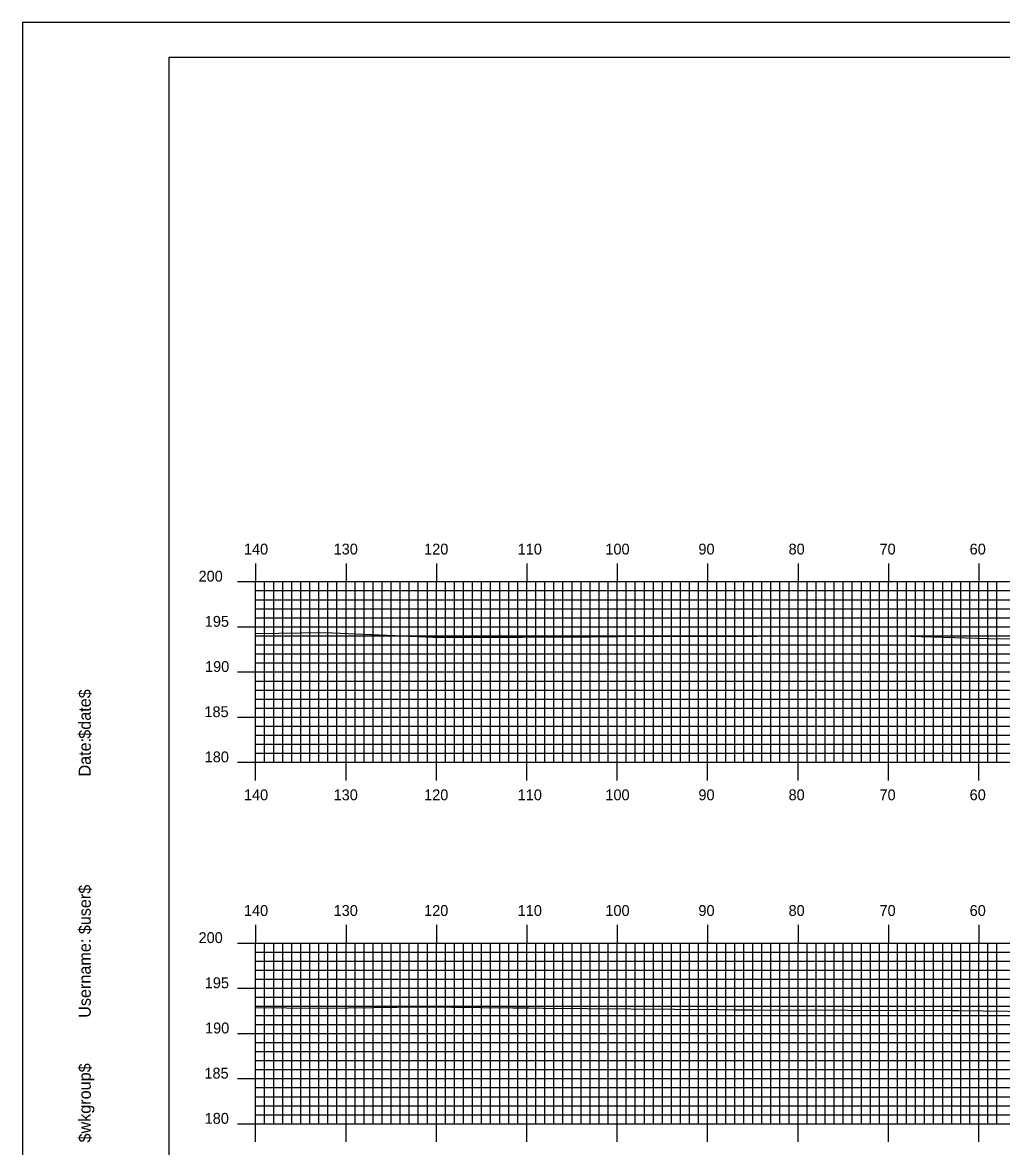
# Model space of a CAD drawing. Extents: x 1798781 to 1799124, y 442591 to 442811.
# Drawn here: x 1798781.2 to 1798889.5, y 442686.2 to 442810.5 of the extents above; entities that cross this region are included whole.
import ezdxf

# ---------------------------------------------------------------- set-up
doc = ezdxf.new("R2010")
doc.units = 0
for name, color, linetype in [('BORDER', 7, 'Continuous'), ('H_V ANNOTATION', 7, 'Continuous'), ('MAJOR', 7, 'Continuous'), ('MINOR', 7, 'Continuous'), ('PLOT BOUNDARY', 7, 'Continuous'), ('S_Roadway_Centerline', 7, 'Continuous')]:
    doc.layers.add(name, color=color, linetype=linetype)

msp = doc.modelspace()

# ---------------------------------------------------------------- linework, layer by layer
at = {"layer": 'BORDER'}
msp.add_lwpolyline([(1798797.38, 442596.67), (1799117.38, 442596.67), (1799117.38, 442806.67), (1798797.38, 442806.67)], close=True, dxfattribs=at)
at = {"layer": 'MAJOR'}
for p, q in [((1798806.98, 442750.67), (1798806.98, 442748.67)), ((1798816.98, 442750.67), (1798816.98, 442748.67)), ((1798826.98, 442750.67), (1798826.98, 442748.67)), ((1798836.98, 442750.67), (1798836.98, 442748.67)), ((1798846.98, 442750.67), (1798846.98, 442748.67)), ((1798856.98, 442750.67), (1798856.98, 442748.67)), ((1798866.98, 442750.67), (1798866.98, 442748.67)), ((1798876.98, 442750.67), (1798876.98, 442748.67)), ((1798886.98, 442750.67), (1798886.98, 442748.67)), ((1798804.98, 442748.67), (1798806.98, 442748.67)), ((1798806.98, 442748.67), (1799086.98, 442748.67)), ((1798806.98, 442728.67), (1798806.98, 442748.67)), ((1798806.98, 442728.67), (1798806.98, 442748.67)), ((1798806.98, 442748.67), (1799086.98, 442748.67)), ((1798816.98, 442728.67), (1798816.98, 442748.67)), ((1798826.98, 442728.67), (1798826.98, 442748.67)), ((1798836.98, 442728.67), (1798836.98, 442748.67)), ((1798846.98, 442728.67), (1798846.98, 442748.67)), ((1798856.98, 442728.67), (1798856.98, 442748.67)), ((1798866.98, 442728.67), (1798866.98, 442748.67)), ((1798876.98, 442728.67), (1798876.98, 442748.67)), ((1798886.98, 442728.67), (1798886.98, 442748.67)), ((1798804.98, 442743.67), (1798806.98, 442743.67)), ((1798806.98, 442743.67), (1799086.98, 442743.67)), ((1798804.98, 442738.67), (1798806.98, 442738.67)), ((1798806.98, 442738.67), (1799086.98, 442738.67)), ((1798804.98, 442733.67), (1798806.98, 442733.67)), ((1798806.98, 442733.67), (1799086.98, 442733.67)), ((1798804.98, 442728.67), (1798806.98, 442728.67)), ((1798806.98, 442728.67), (1799086.98, 442728.67)), ((1798806.98, 442728.67), (1799086.98, 442728.67)), ((1798806.98, 442726.66), (1798806.98, 442728.67)), ((1798816.98, 442726.66), (1798816.98, 442728.67)), ((1798826.98, 442726.66), (1798826.98, 442728.67)), ((1798836.98, 442726.66), (1798836.98, 442728.67)), ((1798846.98, 442726.66), (1798846.98, 442728.67)), ((1798856.98, 442726.66), (1798856.98, 442728.67)), ((1798866.98, 442726.66), (1798866.98, 442728.67)), ((1798876.98, 442726.66), (1798876.98, 442728.67)), ((1798886.98, 442726.66), (1798886.98, 442728.67)), ((1798806.98, 442710.67), (1798806.98, 442708.67)), ((1798816.98, 442710.67), (1798816.98, 442708.67)), ((1798826.98, 442710.67), (1798826.98, 442708.67)), ((1798836.98, 442710.67), (1798836.98, 442708.67)), ((1798846.98, 442710.67), (1798846.98, 442708.67)), ((1798856.98, 442710.67), (1798856.98, 442708.67)), ((1798866.98, 442710.67), (1798866.98, 442708.67)), ((1798876.98, 442710.67), (1798876.98, 442708.67)), ((1798886.98, 442710.67), (1798886.98, 442708.67)), ((1798804.98, 442708.67), (1798806.98, 442708.67)), ((1798806.98, 442708.67), (1799086.98, 442708.67)), ((1798806.98, 442688.67), (1798806.98, 442708.67)), ((1798806.98, 442688.67), (1798806.98, 442708.67)), ((1798806.98, 442708.67), (1799086.98, 442708.67)), ((1798816.98, 442688.67), (1798816.98, 442708.67)), ((1798826.98, 442688.67), (1798826.98, 442708.67)), ((1798836.98, 442688.67), (1798836.98, 442708.67)), ((1798846.98, 442688.67), (1798846.98, 442708.67)), ((1798856.98, 442688.67), (1798856.98, 442708.67)), ((1798866.98, 442688.67), (1798866.98, 442708.67)), ((1798876.98, 442688.67), (1798876.98, 442708.67)), ((1798886.98, 442688.67), (1798886.98, 442708.67)), ((1798804.98, 442703.67), (1798806.98, 442703.67)), ((1798806.98, 442703.67), (1799086.98, 442703.67)), ((1798804.98, 442698.67), (1798806.98, 442698.67)), ((1798806.98, 442698.67), (1799086.98, 442698.67)), ((1798804.98, 442693.67), (1798806.98, 442693.67)), ((1798806.98, 442693.67), (1799086.98, 442693.67)), ((1798804.98, 442688.67), (1798806.98, 442688.67)), ((1798806.98, 442688.67), (1799086.98, 442688.67)), ((1798806.98, 442688.67), (1799086.98, 442688.67)), ((1798806.98, 442686.66), (1798806.98, 442688.67)), ((1798816.98, 442686.66), (1798816.98, 442688.67)), ((1798826.98, 442686.66), (1798826.98, 442688.67)), ((1798836.98, 442686.66), (1798836.98, 442688.67)), ((1798846.98, 442686.66), (1798846.98, 442688.67)), ((1798856.98, 442686.66), (1798856.98, 442688.67)), ((1798866.98, 442686.66), (1798866.98, 442688.67)), ((1798876.98, 442686.66), (1798876.98, 442688.67)), ((1798886.98, 442686.66), (1798886.98, 442688.67))]:
    msp.add_line(p, q, dxfattribs=at)
at = {"layer": 'MINOR'}
for p, q in [((1798807.98, 442728.67), (1798807.98, 442748.67)), ((1798808.98, 442728.67), (1798808.98, 442748.67)), ((1798809.98, 442728.67), (1798809.98, 442748.67)), ((1798810.98, 442728.67), (1798810.98, 442748.67)), ((1798811.98, 442728.67), (1798811.98, 442748.67)), ((1798812.98, 442728.67), (1798812.98, 442748.67)), ((1798813.98, 442728.67), (1798813.98, 442748.67)), ((1798814.98, 442728.67), (1798814.98, 442748.67)), ((1798815.98, 442728.67), (1798815.98, 442748.67)), ((1798817.98, 442728.67), (1798817.98, 442748.67)), ((1798818.98, 442728.67), (1798818.98, 442748.67)), ((1798819.98, 442728.67), (1798819.98, 442748.67)), ((1798820.98, 442728.67), (1798820.98, 442748.67)), ((1798821.98, 442728.67), (1798821.98, 442748.67)), ((1798822.98, 442728.67), (1798822.98, 442748.67)), ((1798823.98, 442728.67), (1798823.98, 442748.67)), ((1798824.98, 442728.67), (1798824.98, 442748.67)), ((1798825.98, 442728.67), (1798825.98, 442748.67)), ((1798827.98, 442728.67), (1798827.98, 442748.67)), ((1798828.98, 442728.67), (1798828.98, 442748.67)), ((1798829.98, 442728.67), (1798829.98, 442748.67)), ((1798830.98, 442728.67), (1798830.98, 442748.67)), ((1798831.98, 442728.67), (1798831.98, 442748.67)), ((1798832.98, 442728.67), (1798832.98, 442748.67)), ((1798833.98, 442728.67), (1798833.98, 442748.67)), ((1798834.98, 442728.67), (1798834.98, 442748.67)), ((1798835.98, 442728.67), (1798835.98, 442748.67)), ((1798837.98, 442728.67), (1798837.98, 442748.67)), ((1798838.98, 442728.67), (1798838.98, 442748.67)), ((1798839.98, 442728.67), (1798839.98, 442748.67)), ((1798840.98, 442728.67), (1798840.98, 442748.67)), ((1798841.98, 442728.67), (1798841.98, 442748.67)), ((1798842.98, 442728.67), (1798842.98, 442748.67)), ((1798843.98, 442728.67), (1798843.98, 442748.67)), ((1798844.98, 442728.67), (1798844.98, 442748.67)), ((1798845.98, 442728.67), (1798845.98, 442748.67)), ((1798847.98, 442728.67), (1798847.98, 442748.67)), ((1798848.98, 442728.67), (1798848.98, 442748.67)), ((1798849.98, 442728.67), (1798849.98, 442748.67)), ((1798850.98, 442728.67), (1798850.98, 442748.67)), ((1798851.98, 442728.67), (1798851.98, 442748.67)), ((1798852.98, 442728.67), (1798852.98, 442748.67)), ((1798853.98, 442728.67), (1798853.98, 442748.67)), ((1798854.98, 442728.67), (1798854.98, 442748.67)), ((1798855.98, 442728.67), (1798855.98, 442748.67)), ((1798857.98, 442728.67), (1798857.98, 442748.67)), ((1798858.98, 442728.67), (1798858.98, 442748.67)), ((1798859.98, 442728.67), (1798859.98, 442748.67)), ((1798860.98, 442728.67), (1798860.98, 442748.67)), ((1798861.98, 442728.67), (1798861.98, 442748.67)), ((1798862.98, 442728.67), (1798862.98, 442748.67)), ((1798863.98, 442728.67), (1798863.98, 442748.67)), ((1798864.98, 442728.67), (1798864.98, 442748.67)), ((1798865.98, 442728.67), (1798865.98, 442748.67)), ((1798867.98, 442728.67), (1798867.98, 442748.67)), ((1798868.98, 442728.67), (1798868.98, 442748.67)), ((1798869.98, 442728.67), (1798869.98, 442748.67)), ((1798870.98, 442728.67), (1798870.98, 442748.67)), ((1798871.98, 442728.67), (1798871.98, 442748.67)), ((1798872.98, 442728.67), (1798872.98, 442748.67)), ((1798873.98, 442728.67), (1798873.98, 442748.67)), ((1798874.98, 442728.67), (1798874.98, 442748.67)), ((1798875.98, 442728.67), (1798875.98, 442748.67)), ((1798877.98, 442728.67), (1798877.98, 442748.67)), ((1798878.98, 442728.67), (1798878.98, 442748.67)), ((1798879.98, 442728.67), (1798879.98, 442748.67)), ((1798880.98, 442728.67), (1798880.98, 442748.67)), ((1798881.98, 442728.67), (1798881.98, 442748.67)), ((1798882.98, 442728.67), (1798882.98, 442748.67)), ((1798883.98, 442728.67), (1798883.98, 442748.67)), ((1798884.98, 442728.67), (1798884.98, 442748.67)), ((1798885.98, 442728.67), (1798885.98, 442748.67)), ((1798887.98, 442728.67), (1798887.98, 442748.67)), ((1798888.98, 442728.67), (1798888.98, 442748.67)), ((1798806.98, 442747.67), (1799086.98, 442747.67)), ((1798806.98, 442747.67), (1798808.99, 442747.67)), ((1798806.98, 442746.67), (1799086.98, 442746.67)), ((1798806.98, 442746.67), (1798808.99, 442746.67)), ((1798806.98, 442745.67), (1799086.98, 442745.67)), ((1798806.98, 442745.67), (1798808.99, 442745.67)), ((1798806.98, 442744.67), (1799086.98, 442744.67)), ((1798806.98, 442744.67), (1798808.99, 442744.67)), ((1798806.98, 442742.67), (1799086.98, 442742.67)), ((1798806.98, 442742.67), (1798808.99, 442742.67)), ((1798806.98, 442741.67), (1799086.98, 442741.67)), ((1798806.98, 442741.67), (1798808.99, 442741.67)), ((1798806.98, 442740.67), (1799086.98, 442740.67)), ((1798806.98, 442740.67), (1798808.99, 442740.67)), ((1798806.98, 442739.67), (1799086.98, 442739.67)), ((1798806.98, 442739.67), (1798808.99, 442739.67)), ((1798806.98, 442737.67), (1799086.98, 442737.67)), ((1798806.98, 442737.67), (1798808.99, 442737.67)), ((1798806.98, 442736.67), (1799086.98, 442736.67)), ((1798806.98, 442736.67), (1798808.99, 442736.67)), ((1798806.98, 442735.67), (1799086.98, 442735.67)), ((1798806.98, 442735.67), (1798808.99, 442735.67)), ((1798806.98, 442734.67), (1799086.98, 442734.67)), ((1798806.98, 442734.67), (1798808.99, 442734.67)), ((1798806.98, 442732.67), (1799086.98, 442732.67)), ((1798806.98, 442732.67), (1798808.99, 442732.67)), ((1798806.98, 442731.67), (1799086.98, 442731.67)), ((1798806.98, 442731.67), (1798808.99, 442731.67)), ((1798806.98, 442730.67), (1799086.98, 442730.67)), ((1798806.98, 442730.67), (1798808.99, 442730.67)), ((1798806.98, 442729.67), (1799086.98, 442729.67)), ((1798806.98, 442729.67), (1798808.99, 442729.67)), ((1798807.98, 442688.67), (1798807.98, 442708.67)), ((1798808.98, 442688.67), (1798808.98, 442708.67)), ((1798809.98, 442688.67), (1798809.98, 442708.67)), ((1798810.98, 442688.67), (1798810.98, 442708.67)), ((1798811.98, 442688.67), (1798811.98, 442708.67)), ((1798812.98, 442688.67), (1798812.98, 442708.67)), ((1798813.98, 442688.67), (1798813.98, 442708.67)), ((1798814.98, 442688.67), (1798814.98, 442708.67)), ((1798815.98, 442688.67), (1798815.98, 442708.67)), ((1798817.98, 442688.67), (1798817.98, 442708.67)), ((1798818.98, 442688.67), (1798818.98, 442708.67)), ((1798819.98, 442688.67), (1798819.98, 442708.67)), ((1798820.98, 442688.67), (1798820.98, 442708.67)), ((1798821.98, 442688.67), (1798821.98, 442708.67)), ((1798822.98, 442688.67), (1798822.98, 442708.67)), ((1798823.98, 442688.67), (1798823.98, 442708.67)), ((1798824.98, 442688.67), (1798824.98, 442708.67)), ((1798825.98, 442688.67), (1798825.98, 442708.67)), ((1798827.98, 442688.67), (1798827.98, 442708.67)), ((1798828.98, 442688.67), (1798828.98, 442708.67)), ((1798829.98, 442688.67), (1798829.98, 442708.67)), ((1798830.98, 442688.67), (1798830.98, 442708.67)), ((1798831.98, 442688.67), (1798831.98, 442708.67)), ((1798832.98, 442688.67), (1798832.98, 442708.67)), ((1798833.98, 442688.67), (1798833.98, 442708.67)), ((1798834.98, 442688.67), (1798834.98, 442708.67)), ((1798835.98, 442688.67), (1798835.98, 442708.67)), ((1798837.98, 442688.67), (1798837.98, 442708.67)), ((1798838.98, 442688.67), (1798838.98, 442708.67)), ((1798839.98, 442688.67), (1798839.98, 442708.67)), ((1798840.98, 442688.67), (1798840.98, 442708.67)), ((1798841.98, 442688.67), (1798841.98, 442708.67)), ((1798842.98, 442688.67), (1798842.98, 442708.67)), ((1798843.98, 442688.67), (1798843.98, 442708.67)), ((1798844.98, 442688.67), (1798844.98, 442708.67)), ((1798845.98, 442688.67), (1798845.98, 442708.67)), ((1798847.98, 442688.67), (1798847.98, 442708.67)), ((1798848.98, 442688.67), (1798848.98, 442708.67)), ((1798849.98, 442688.67), (1798849.98, 442708.67)), ((1798850.98, 442688.67), (1798850.98, 442708.67)), ((1798851.98, 442688.67), (1798851.98, 442708.67)), ((1798852.98, 442688.67), (1798852.98, 442708.67)), ((1798853.98, 442688.67), (1798853.98, 442708.67)), ((1798854.98, 442688.67), (1798854.98, 442708.67)), ((1798855.98, 442688.67), (1798855.98, 442708.67)), ((1798857.98, 442688.67), (1798857.98, 442708.67)), ((1798858.98, 442688.67), (1798858.98, 442708.67)), ((1798859.98, 442688.67), (1798859.98, 442708.67)), ((1798860.98, 442688.67), (1798860.98, 442708.67)), ((1798861.98, 442688.67), (1798861.98, 442708.67)), ((1798862.98, 442688.67), (1798862.98, 442708.67)), ((1798863.98, 442688.67), (1798863.98, 442708.67)), ((1798864.98, 442688.67), (1798864.98, 442708.67)), ((1798865.98, 442688.67), (1798865.98, 442708.67)), ((1798867.98, 442688.67), (1798867.98, 442708.67)), ((1798868.98, 442688.67), (1798868.98, 442708.67)), ((1798869.98, 442688.67), (1798869.98, 442708.67)), ((1798870.98, 442688.67), (1798870.98, 442708.67)), ((1798871.98, 442688.67), (1798871.98, 442708.67)), ((1798872.98, 442688.67), (1798872.98, 442708.67)), ((1798873.98, 442688.67), (1798873.98, 442708.67)), ((1798874.98, 442688.67), (1798874.98, 442708.67)), ((1798875.98, 442688.67), (1798875.98, 442708.67)), ((1798877.98, 442688.67), (1798877.98, 442708.67)), ((1798878.98, 442688.67), (1798878.98, 442708.67)), ((1798879.98, 442688.67), (1798879.98, 442708.67)), ((1798880.98, 442688.67), (1798880.98, 442708.67)), ((1798881.98, 442688.67), (1798881.98, 442708.67)), ((1798882.98, 442688.67), (1798882.98, 442708.67)), ((1798883.98, 442688.67), (1798883.98, 442708.67)), ((1798884.98, 442688.67), (1798884.98, 442708.67)), ((1798885.98, 442688.67), (1798885.98, 442708.67)), ((1798887.98, 442688.67), (1798887.98, 442708.67)), ((1798888.98, 442688.67), (1798888.98, 442708.67)), ((1798806.98, 442707.67), (1799086.98, 442707.67)), ((1798806.98, 442707.67), (1798808.99, 442707.67)), ((1798806.98, 442706.67), (1799086.98, 442706.67)), ((1798806.98, 442706.67), (1798808.99, 442706.67)), ((1798806.98, 442705.67), (1799086.98, 442705.67)), ((1798806.98, 442705.67), (1798808.99, 442705.67)), ((1798806.98, 442704.67), (1799086.98, 442704.67)), ((1798806.98, 442704.67), (1798808.99, 442704.67)), ((1798806.98, 442702.67), (1799086.98, 442702.67)), ((1798806.98, 442702.67), (1798808.99, 442702.67)), ((1798806.98, 442701.67), (1799086.98, 442701.67)), ((1798806.98, 442701.67), (1798808.99, 442701.67)), ((1798806.98, 442700.67), (1799086.98, 442700.67)), ((1798806.98, 442700.67), (1798808.99, 442700.67)), ((1798806.98, 442699.67), (1799086.98, 442699.67)), ((1798806.98, 442699.67), (1798808.99, 442699.67)), ((1798806.98, 442697.67), (1799086.98, 442697.67)), ((1798806.98, 442697.67), (1798808.99, 442697.67)), ((1798806.98, 442696.67), (1799086.98, 442696.67)), ((1798806.98, 442696.67), (1798808.99, 442696.67)), ((1798806.98, 442695.67), (1799086.98, 442695.67)), ((1798806.98, 442695.67), (1798808.99, 442695.67)), ((1798806.98, 442694.67), (1799086.98, 442694.67)), ((1798806.98, 442694.67), (1798808.99, 442694.67)), ((1798806.98, 442692.67), (1799086.98, 442692.67)), ((1798806.98, 442692.67), (1798808.99, 442692.67)), ((1798806.98, 442691.67), (1799086.98, 442691.67)), ((1798806.98, 442691.67), (1798808.99, 442691.67)), ((1798806.98, 442690.67), (1799086.98, 442690.67)), ((1798806.98, 442690.67), (1798808.99, 442690.67)), ((1798806.98, 442689.67), (1799086.98, 442689.67)), ((1798806.98, 442689.67), (1798808.99, 442689.67))]:
    msp.add_line(p, q, dxfattribs=at)
at = {"layer": 'PLOT BOUNDARY'}
msp.add_lwpolyline([(1798781.2, 442590.55), (1799121.2, 442590.55), (1799121.2, 442810.55), (1798781.2, 442810.55)], close=True, dxfattribs=at)
at = {"layer": 'S_Roadway_Centerline'}
for points in [[(1798806.98, 442742.93), (1798814.59, 442743.05), (1798816.37, 442742.97), (1798826.66, 442742.53), (1798836.46, 442742.51), (1798838.54, 442742.55), (1798840.66, 442742.54), (1798850.29, 442742.64), (1798859.97, 442742.63), (1798862.45, 442742.63), (1798864.97, 442742.66), (1798878.13, 442742.66), (1798888.06, 442742.38), (1798896.78, 442742.31)], [(1798806.98, 442701.52), (1798810.4, 442701.49), (1798814.03, 442701.48), (1798817.22, 442701.5), (1798825.29, 442701.62), (1798835.42, 442701.5), (1798837.24, 442701.49), (1798838.79, 442701.48), (1798858.2, 442701.32), (1798860.07, 442701.29), (1798861.97, 442701.27), (1798872.46, 442701.26), (1798883.96, 442701.21), (1798884.74, 442701.2), (1798898.44, 442701.03)]]:
    msp.add_lwpolyline(points, dxfattribs=at)

# ---------------------------------------------------------------- texts
at = {"layer": 'BORDER'}
for s, p in [('$date$', (1798788.75, 442731.28)), ('Date:', (1798788.75, 442727.1)), ('$user$', (1798788.75, 442709.65)), ('Username:', (1798788.75, 442700.4)), ('$wkgroup$', (1798788.75, 442686.6))]:
    msp.add_text(s, height=1.339, rotation=90, dxfattribs=at).set_placement(p)
at = {"layer": 'H_V ANNOTATION'}
for s, p in [('140', (1798805.69, 442751.67)), ('130', (1798815.61, 442751.67)), ('120', (1798825.62, 442751.67)), ('110', (1798835.97, 442751.67)), ('100', (1798845.67, 442751.67)), ('90', (1798855.96, 442751.67)), ('80', (1798865.93, 442751.67)), ('70', (1798875.99, 442751.67)), ('60', (1798885.96, 442751.67)), ('200', (1798800.67, 442748.67)), ('195', (1798801.36, 442743.67)), ('190', (1798801.39, 442738.67)), ('185', (1798801.32, 442733.67)), ('180', (1798801.35, 442728.67)), ('140', (1798805.69, 442724.47)), ('130', (1798815.61, 442724.47)), ('120', (1798825.62, 442724.47)), ('110', (1798835.97, 442724.47)), ('100', (1798845.67, 442724.47)), ('90', (1798855.96, 442724.47)), ('80', (1798865.93, 442724.47)), ('70', (1798875.99, 442724.47)), ('60', (1798885.96, 442724.47)), ('140', (1798805.69, 442711.67)), ('130', (1798815.61, 442711.67)), ('120', (1798825.62, 442711.67)), ('110', (1798835.97, 442711.67)), ('100', (1798845.67, 442711.67)), ('90', (1798855.96, 442711.67)), ('80', (1798865.93, 442711.67)), ('70', (1798875.99, 442711.67)), ('60', (1798885.96, 442711.67)), ('200', (1798800.67, 442708.67)), ('195', (1798801.36, 442703.67)), ('190', (1798801.39, 442698.67)), ('185', (1798801.32, 442693.67)), ('180', (1798801.35, 442688.67))]:
    msp.add_text(s, height=1.2, dxfattribs=at).set_placement(p)
at = {"layer": 'MAJOR'}
for p in [(1798806.97, 442728.67), (1798806.97, 442688.67)]:
    msp.add_text('-', height=0.012, dxfattribs=at).set_placement(p)

doc.saveas('drawing.dxf')
